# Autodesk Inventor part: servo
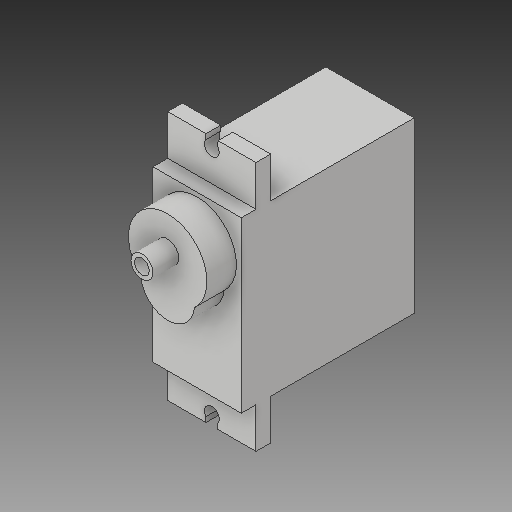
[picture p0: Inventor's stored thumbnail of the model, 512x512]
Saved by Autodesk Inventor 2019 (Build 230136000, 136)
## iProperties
Created: 2020-02
Part Number: servo
Material: Generic
Document SubType Name: Modeling
Designer: shivu
Density: 1 g/cm^3
Appearance: Default
Author: shivu
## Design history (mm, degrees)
sketch "Sketch1"
  geometry: L1 (0, 0)-(12, 0); L2 (12, 0)-(12, 23); L3 (12, 23)-(0, 23); L4 (0, 23)-(0, 0)
  constraints: 8 end point, 2 parallel, 1 horizontal, 1 perpendicular
  dimensions: "d0" = 12 distance of L3.end L2.end; "d1" = 23 distance of L2.end L1.end
extrude "Extrusion1" new body sketch "Sketch1" distance "d2" = 23.5; taper "d3" = 0 deg
sketch "Sketch2"
  geometry: A1 r 5.33 centre (6, 17.139) between (9.655, 13.26) and (2.345, 13.26); A2 r 3.671 centre (6, 13.6) between (2.345, 13.26) and (9.655, 13.26); 1 further point
  constraints: 4 point on circle, 2 centre point
extrude "Extrusion2" join sketch "Sketch2" distance "d4" = 4; taper "d5" = 0 deg
sketch "Sketch3"
  geometry: C1 r 1.5 at (6, 18.01); 1 further point
  constraints: 1 centre point
extrude "Extrusion3" join sketch "Sketch3" distance "d7" = 3.5; taper "d8" = 0 deg
sketch "Sketch4"
  geometry: C1 r 1 at (0, 0); 2 further points
  constraints: 1 centre point, 1 coincident
extrude "Extrusion4" cut sketch "Sketch4" distance "d10" = 3.5; taper "d11" = 0 deg
sketch "Sketch5"
  geometry: L1 (0, 19.5)-(12, 19.5); L2 (12, 19.5)-(12, 21.5); L3 (12, 21.5)-(0, 21.5); L4 (0, 21.5)-(0, 19.5); 1 further point
  constraints: 8 end point, 2 parallel, 1 horizontal, 1 perpendicular
  dimensions: "d13" = 12 distance of L3.end L2.end; "d14" = 2 distance of L2.end L1.end
extrude "Extrusion5" join sketch "Sketch5" distance "d15" = 5.5; taper "d16" = 0 deg
sketch "Sketch6"
  geometry: L1 (5.204, -4.796)-(5.204, -5.5); L2 (0, -5.5)-(12, -5.5) reference; L3 (6.796, -4.796)-(6.796, -5.5); A1 r 1 centre (6, -4.19) between (6.796, -4.796) and (5.204, -4.796); 1 further point
  constraints: 4 end point, 2 point on circle, 2 point on line, 1 centre point, 1 parallel, 1 vertical
  dimensions: "d17" = 2 diameter of A1
extrude "Extrusion6" cut sketch "Sketch6" distance "d18" = 2; taper "d19" = 0 deg
sketch "Sketch7"
  geometry: L1 (12, -19.5)-(12, -21.5); L2 (12, -21.5)-(0, -21.5); L3 (0, -21.5)-(0, -19.5); L4 (12, -19.5)-(0, -19.5)
  constraints: 8 end point, 1 horizontal, 1 parallel
  dimensions: "d20" = 12 distance of L1.end L2.end; "d21" = 2 distance of L1.start L1.end
extrude "Extrusion7" join sketch "Sketch7" distance "d22" = 5.5; taper "d23" = 0 deg
sketch "Sketch8"
  geometry: L1 (5.205, 4.796)-(5.205, 5.5); L2 (6.796, 4.796)-(6.845, 5.5); L3 (5.205, 5.5)-(6.845, 5.5); A1 r 1 centre (6, 4.19) between (5.205, 4.796) and (6.796, 4.796); 1 further point
  constraints: 6 end point, 2 point on circle, 1 centre point
  dimensions: "d25" = 2 diameter of A1
extrude "Extrusion8" cut sketch "Sketch8" distance "d29" = 2; taper "d30" = 0 deg
body "Solid1"
